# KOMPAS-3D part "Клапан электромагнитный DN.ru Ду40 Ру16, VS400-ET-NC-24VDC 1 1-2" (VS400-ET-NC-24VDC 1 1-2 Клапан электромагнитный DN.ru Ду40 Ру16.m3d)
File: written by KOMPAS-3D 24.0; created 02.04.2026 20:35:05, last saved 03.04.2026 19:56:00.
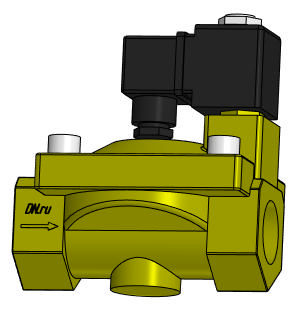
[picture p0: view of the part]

Document properties: Автор: artio; Полное имя файла: C:\Users\artio\OneDrive\Рабочий стол\Клапан электромагнитный DN.ru\VS400-ET-NC\VS400-ET-NC-24VDC 1 1-2 Клапан электромагнитный DN.ru Ду40 Ру16.m3d

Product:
- Body: Тело 1  | qty 1
    Масса: 4.144257
- Part/product: Клапан электромагнитный DN.ru Ду40 Ру16  | designation VS400-ET-NC-24VDC 1 1-2
    Масса: 2.321
    Раздел спецификации: Прочие изделия
    Примечание: D130-04723
    additional columns: ef56311e-7521-43dc-8291-0e6108b3d81d; VS400-ET-NC-220VAC 1 1-2; artio; c; Шероховатость не задана; Да

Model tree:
1. Операция без истории:1

Expressions: VS400-ET-NC-24VDC 1 1-2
